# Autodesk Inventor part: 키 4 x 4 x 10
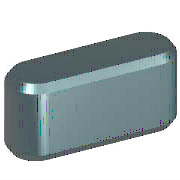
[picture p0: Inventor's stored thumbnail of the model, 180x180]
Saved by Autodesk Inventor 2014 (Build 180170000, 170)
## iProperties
IsCustomPart: 1
Created: 2012-02
Part Number: 키 4 x 4 x 10
Material: 강철, 연강
Description: 키 및 해당 키홈
Document SubType Name: Modeling
Standard: KS B 1311
Designer: test
Standards Organization: KS
Language: ko-KR
Size Designation: 4 x 4 x 10
Categories: <MemberInstance><Categories><Category DisplayName="샤프트 부품" InternalName="7f7aeb1f-a693-4053-b835-cee3144e0d98" Mnemonic="SHFT"><Category DisplayName="키" Interna
Density: 1 g/cm^3
Appearance: 강철
Author: test
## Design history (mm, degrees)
workplane "Work Plane1"
workplane "Work Plane2"
sketch "스케치1"
  geometry: L1 (2, 2)-(8, 2); L2 (8, -2)-(2, -2); L3 (0, 9.4)-(0, -7.4) reference; L4 (-5, 0)-(30, 0) reference; L5 (10, 0)-(10, 7); A1 r 2 centre (2, 0) between (2, 2) and (2, -2); A2 r 2 centre (8, 0) between (8, -2) and (8, 2)
  constraints: 6 end point, 5 point on circle, 4 tangent, 3 point on line, 2 centre point, 1 horizontal, 1 parallel, 1 perpendicular
  dimensions: "d0" = 2 radius of A1 (= 0.5 x PB); "d13" = 2 radius of A2 (= 0.5 x PB); "d14" = 10 distance between parallel lines of L5 L3 (= NLG)
extrude "본체1" new body sketch "스케치1" taper "d3" = 0 deg; stored distance "d4" = 10
workplane "Work Plane3"
body "Solid1"
chamfer "모따기1" distance "d8" = 0.25 (= PHH); stored, may be unused: second distance "d9" = 0.25 (= PHH), angle "d15" = 45 deg
other parameters: "d1" = -2.5 (= -PNT), "d2" = 1.5 (= PH - PNT), "NLG" = 10 [user parameter; used in 3 equation terms], "PB" = 4 [user parameter; used in 2 equation terms], "PNT" = 2.5 [user parameter; used in 2 equation terms], "PH" = 4 [user parameter; used in 1 equation term], "PHH" = 0.25 [user parameter; used in 2 equation terms], "d10" = 0, "d16" = 0, "d17" = 0, "d18" = 0, "WDMAX" = 12 [user parameter], "RR" = 0.08 [user parameter], "PUEB" = 1.8 [user parameter]
